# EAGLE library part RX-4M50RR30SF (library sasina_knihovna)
Prijimaci modul pro 433MHz
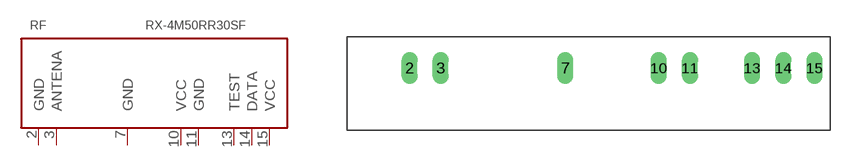
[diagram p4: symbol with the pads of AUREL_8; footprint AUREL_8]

Designator prefix RF

## RX-4M50RR30SF  [AUREL_8]
2  GND  sup
3  ANTENA  in
7  GND  sup
10  VCC  sup
11  GND  sup
13  TEST  pas
14  DATA  out
15  VCC  sup

## Footprint AUREL_8 (pad centres in mm)
drill 0.8 long: 2 -17.78,1.27; 3 -15.24,1.27; 7 -5.08,1.27; 10 2.54,1.27; 11 5.08,1.27; 13 10.16,1.27; 14 12.7,1.27; 15 15.24,1.27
